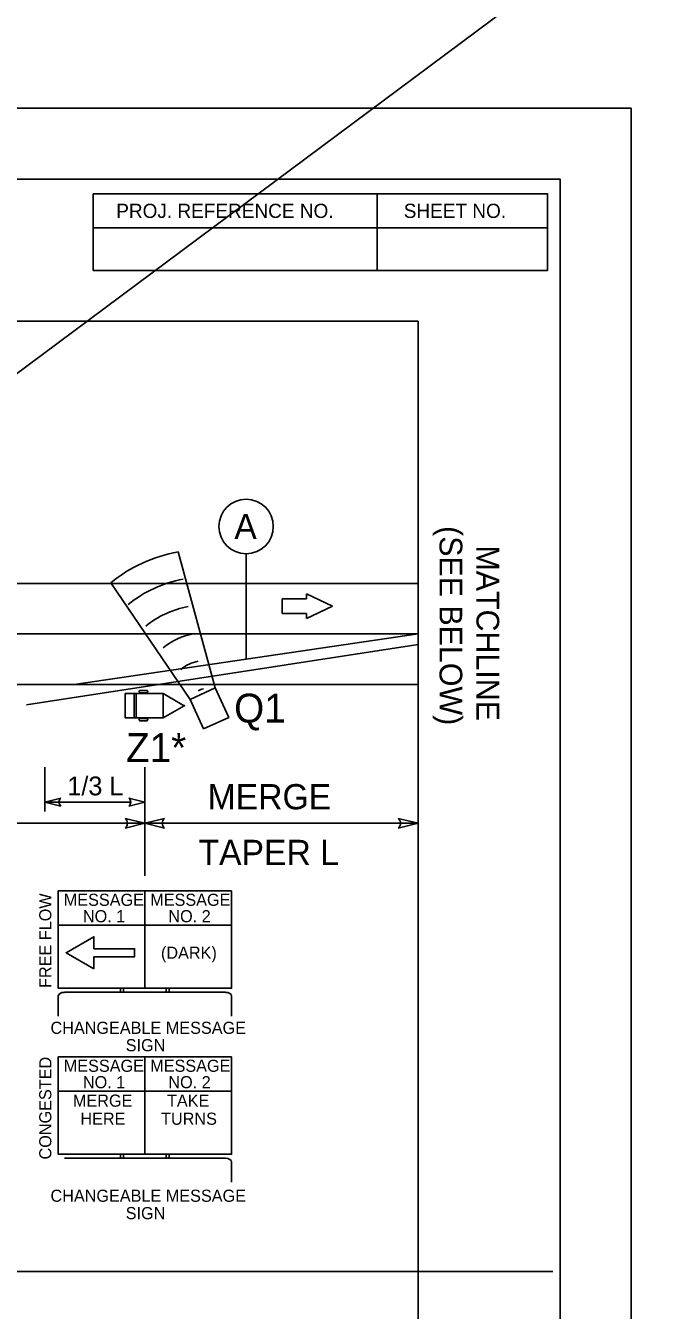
# Model space of a CAD drawing. Extents: x 1379436 to 1387057, y 792703 to 795604.
# Drawn here: x 1382289 to 1382626, y 794247 to 794926 of the extents above; entities that cross this region are included whole.
import ezdxf

# ---------------------------------------------------------------- set-up
doc = ezdxf.new("R2010")
doc.units = 0
for name, color, linetype in [('Black Area Fill Shapes', 7, 'Continuous'), ('Default', 7, 'Continuous'), ('DEV BORDER CELL', 7, 'Continuous'), ('DEV CMS PLAN VIEW CELL', 7, 'Continuous'), ('DEV CMS TEXT CELL', 7, 'Continuous'), ('DEV DIRECTION OF TRAFFIC FLOW ARROW CELL', 7, 'Continuous'), ('DEV LINE TERMINATOR TYPE 3 CELL', 7, 'Continuous'), ('Drum Linestyle', 7, 'Continuous'), ('Gray Area Fill Shapes', 7, 'Continuous'), ('Prop Mkg Skp Wht', 7, 'Continuous'), ('Prop Mkg Solid White Lane Line', 7, 'Continuous'), ('Prop Mkg Solid Yellow Edge Line', 7, 'Continuous'), ('Scratch_Level_0', 7, 'Continuous'), ('Sheet Plot Border Outside CELL', 7, 'Continuous'), ('Text', 7, 'Continuous')]:
    doc.layers.add(name, color=color, linetype=linetype)

msp = doc.modelspace()

# ---------------------------------------------------------------- linework, layer by layer
at = {"layer": 'Black Area Fill Shapes'}
msp.add_lwpolyline([(1382382.51, 794554.35), (1382375.35, 794569.89), (1382388.66, 794576.02), (1382395.82, 794560.48)], close=True, dxfattribs=at)
at = {"layer": 'Default'}
for p, q in [((1379547.85, 792703.35), (1383441.11, 795604.31)), ((1382495.75, 794522.98), (1382495.75, 794686.06)), ((1382404.97, 794591.19), (1382404.97, 794646.92)), ((1382298.74, 794534.09), (1382298.74, 794510.68)), ((1382351.53, 794534.09), (1382351.53, 794476.77)), ((1382495.75, 794534.09), (1382495.75, 794476.77)), ((1382298.74, 794515.71), (1382344.07, 794515.71)), ((1380845.89, 794504.52), (1382495.75, 794504.52)), ((1380316.98, 794267.83), (1382566.98, 794267.84))]:
    msp.add_line(p, q, dxfattribs=at)
msp.add_circle((1382404.97, 794661.28), 14.37, dxfattribs=at)
at = {"layer": 'DEV BORDER CELL'}
msp.add_line((1382474.23, 794819), (1382564.22, 794819), dxfattribs=at)
for points in [[(1382570.75, 794844.71), (1380320.75, 794844.71), (1380320.75, 793269.71), (1382570.75, 793269.71)], [(1382324.22, 794837), (1382474.23, 794837), (1382474.23, 794819), (1382324.22, 794819)], [(1382474.23, 794819), (1382564.22, 794819), (1382564.22, 794837), (1382474.23, 794837)], [(1382474.23, 794819), (1382324.22, 794819), (1382324.22, 794796.5), (1382474.23, 794796.5)], [(1382474.23, 794819), (1382564.22, 794819), (1382564.22, 794796.5), (1382474.23, 794796.5)]]:
    msp.add_lwpolyline(points, close=True, dxfattribs=at)
at = {"layer": 'DEV CMS PLAN VIEW CELL'}
for p, q in [((1382341.11, 794573.06), (1382341.11, 794560.14)), ((1382341.11, 794573.05), (1382361.1, 794573.05)), ((1382341.11, 794560.13), (1382341.11, 794573.05)), ((1382345.78, 794560.13), (1382345.78, 794573.05)), ((1382346.85, 794560.13), (1382346.85, 794573.05)), ((1382348.66, 794574.69), (1382352.79, 794574.69)), ((1382348.66, 794573.46), (1382352.79, 794573.46)), ((1382361.1, 794560.14), (1382361.1, 794573.05)), ((1382361.1, 794573.05), (1382372.29, 794566.6)), ((1382361.1, 794560.14), (1382372.29, 794566.6)), ((1382341.11, 794560.14), (1382361.1, 794560.14)), ((1382348.66, 794559.88), (1382352.79, 794559.88)), ((1382348.66, 794558.7), (1382352.79, 794558.7))]:
    msp.add_line(p, q, dxfattribs=at)
msp.add_circle((1382372.4, 794566.58), 0.114, dxfattribs=at)
for centre, start, end in [((1382349.41, 794574.05), 142.08835, 217.91165), ((1382352.03, 794574.05), 322.08835, 37.91165), ((1382349.41, 794559.29), 142.08835, 217.91165), ((1382352.03, 794559.29), 322.08835, 37.91165)]:
    msp.add_arc(centre, 0.954, start, end, dxfattribs=at)
at = {"layer": 'DEV CMS TEXT CELL'}
for p, q in [((1382305.77, 794468.84), (1382397.29, 794468.84)), ((1382305.77, 794417.37), (1382305.77, 794468.84)), ((1382351.53, 794417.37), (1382351.53, 794468.84)), ((1382351.53, 794417.37), (1382351.53, 794468.84)), ((1382397.29, 794417.37), (1382397.29, 794468.84)), ((1382305.77, 794450.73), (1382351.53, 794450.73)), ((1382397.29, 794450.73), (1382351.53, 794450.73)), ((1382397.29, 794417.37), (1382305.77, 794417.37)), ((1382308.98, 794415.24), (1382394.07, 794415.24)), ((1382338.67, 794417.37), (1382338.67, 794415.24)), ((1382340.25, 794417.37), (1382340.25, 794415.24)), ((1382362.82, 794417.37), (1382362.82, 794415.24)), ((1382364.4, 794417.37), (1382364.4, 794415.24)), ((1382305.77, 794413.24), (1382305.77, 794402.62)), ((1382397.31, 794413.25), (1382397.31, 794402.63)), ((1382305.77, 794381.18), (1382397.29, 794381.18)), ((1382305.77, 794329.7), (1382305.77, 794381.18)), ((1382351.53, 794329.7), (1382351.53, 794381.18)), ((1382351.53, 794329.7), (1382351.53, 794381.18)), ((1382397.29, 794329.7), (1382397.29, 794381.18)), ((1382305.77, 794363.07), (1382351.53, 794363.07)), ((1382397.29, 794363.07), (1382351.53, 794363.07)), ((1382397.29, 794329.7), (1382305.77, 794329.7)), ((1382308.98, 794327.57), (1382394.07, 794327.57)), ((1382338.67, 794329.7), (1382338.67, 794327.57)), ((1382340.25, 794329.7), (1382340.25, 794327.57)), ((1382362.82, 794329.7), (1382362.82, 794327.57)), ((1382364.4, 794329.7), (1382364.4, 794327.57)), ((1382397.31, 794325.59), (1382397.31, 794314.97))]:
    msp.add_line(p, q, dxfattribs=at)
msp.add_lwpolyline([(1382324.6, 794427.67), (1382309.91, 794436.15), (1382324.6, 794444.63), (1382324.6, 794438.28), (1382346.1, 794438.28), (1382346.1, 794434.02), (1382324.6, 794434.02)], close=True, dxfattribs=at)
for centre, major_axis, start_param, end_param in [((1382309, 794413.25), (-3.24, 0), 4.712389, 6.283185), ((1382394.07, 794413.25), (3.24, 0), 0, 1.570796), ((1382394.07, 794325.59), (3.24, 0), 0, 1.570796)]:
    msp.add_ellipse(centre, major_axis=major_axis, ratio=0.606795, start_param=start_param, end_param=end_param, dxfattribs=at)
at = {"layer": 'DEV DIRECTION OF TRAFFIC FLOW ARROW CELL'}
for p, q in [((1382450.55, 794619.24), (1382436.8, 794625.73)), ((1382436.8, 794625.73), (1382436.8, 794623.1)), ((1382424.02, 794623.11), (1382424.01, 794615.4)), ((1382436.8, 794623.1), (1382424.02, 794623.11)), ((1382436.79, 794612.77), (1382450.55, 794619.24)), ((1382424.01, 794615.4), (1382436.79, 794615.39)), ((1382436.79, 794615.39), (1382436.79, 794612.77))]:
    msp.add_line(p, q, dxfattribs=at)
at = {"layer": 'DEV LINE TERMINATOR TYPE 3 CELL'}
for points in [[(1382307.16, 794513.6), (1382298.74, 794515.71), (1382307.16, 794517.81)], [(1382307.16, 794513.6), (1382298.74, 794515.71), (1382307.16, 794517.81)], [(1382343.11, 794513.6), (1382351.53, 794515.71), (1382343.11, 794517.81)], [(1382343.11, 794513.6), (1382351.53, 794515.71), (1382343.11, 794517.81)], [(1382341.14, 794501.92), (1382351.53, 794504.52), (1382341.14, 794507.12)], [(1382341.14, 794501.92), (1382351.53, 794504.52), (1382341.14, 794507.12)], [(1382361.93, 794501.92), (1382351.53, 794504.52), (1382361.93, 794507.12)], [(1382361.93, 794501.92), (1382351.53, 794504.52), (1382361.93, 794507.12)], [(1382485.36, 794501.92), (1382495.75, 794504.52), (1382485.36, 794507.12)], [(1382485.36, 794501.92), (1382495.75, 794504.52), (1382485.36, 794507.12)]]:
    msp.add_lwpolyline(points, dxfattribs=at)
for centre, radius, start, end in [((1382309.01, 794515.71), 2.8, 131.32643, 228.67356), ((1382309.01, 794515.71), 2.8, 131.32643, 228.67356), ((1382341.26, 794515.71), 2.8, 311.32644, 48.67357), ((1382341.26, 794515.71), 2.8, 311.32644, 48.67357), ((1382338.85, 794504.52), 3.46, 311.32644, 48.67357), ((1382338.85, 794504.52), 3.46, 311.32644, 48.67357), ((1382364.21, 794504.52), 3.46, 131.32643, 228.67356), ((1382364.21, 794504.52), 3.46, 131.32643, 228.67356), ((1382483.07, 794504.52), 3.46, 311.32644, 48.67357), ((1382483.07, 794504.52), 3.46, 311.32644, 48.67357)]:
    msp.add_arc(centre, radius, start, end, dxfattribs=at)
at = {"layer": 'Drum Linestyle'}
msp.add_line((1382495.75, 794599.03), (1382289.02, 794567.01), dxfattribs=at)
at = {"layer": 'Gray Area Fill Shapes'}
for points in [[(1382351.53, 794450.73), (1382305.77, 794450.73), (1382305.77, 794417.37), (1382351.53, 794417.37)], [(1382351.53, 794450.73), (1382397.29, 794450.73), (1382397.29, 794417.37), (1382351.53, 794417.37)], [(1382351.53, 794363.07), (1382305.77, 794363.07), (1382305.77, 794329.7), (1382351.53, 794329.7)], [(1382351.53, 794363.07), (1382397.29, 794363.07), (1382397.29, 794329.7), (1382351.53, 794329.7)]]:
    msp.add_lwpolyline(points, close=True, dxfattribs=at)
at = {"layer": 'Prop Mkg Skp Wht'}
msp.add_line((1381406.39, 794604.5), (1382495.75, 794604.51), dxfattribs=at)
at = {"layer": 'Prop Mkg Solid White Lane Line'}
for p, q in [((1382495.75, 794604.51), (1382314.19, 794577.88)), ((1381406.39, 794577.88), (1382495.75, 794577.88))]:
    msp.add_line(p, q, dxfattribs=at)
at = {"layer": 'Prop Mkg Solid Yellow Edge Line'}
msp.add_line((1381406.39, 794631.12), (1382495.75, 794631.12), dxfattribs=at)
at = {"layer": 'Scratch_Level_0'}
msp.add_lwpolyline([(1382495.75, 794769.71), (1380395.75, 794769.71), (1380395.75, 793344.71), (1381714.03, 793344.71), (1381714.03, 793522.11), (1382495.75, 793522.11)], close=True, dxfattribs=at)
at = {"layer": 'Sheet Plot Border Outside CELL'}
msp.add_lwpolyline([(1380076.25, 793232.21), (1382608.25, 793232.21), (1382608.25, 794882.21), (1380076.25, 794882.21)], close=True, dxfattribs=at)
at = {"layer": 'Text'}
for p, q in [((1382388.66, 794576.02), (1382369.02, 794647.92)), ((1382375.35, 794569.89), (1382333.45, 794631.53))]:
    msp.add_line(p, q, dxfattribs=at)
for radius in [79.44, 64.74, 50.04, 35.34, 20.63, 5.93]:
    msp.add_arc((1382383.46, 794569.79), radius, 100.47314, 129.0092, dxfattribs=at)

# ---------------------------------------------------------------- texts
at = {"layer": 'Default'}
for s, p in [('(SEE BELOW)', (1382507.12, 794661.51)), ('MATCHLINE', (1382526.62, 794651.28))]:
    msp.add_text(s, height=12, rotation=270, dxfattribs=at).set_placement(p)
at = {"layer": 'DEV BORDER CELL'}
for s, height, p in [('PROJ. REFERENCE NO.', 7.4988, (1382336.39, 794824.25)), ('SHEET NO.', 7.499, (1382488.22, 794824.25))]:
    msp.add_text(s, height=height, rotation=0.00056, dxfattribs=at).set_placement(p)
at = {"layer": 'DEV CMS TEXT CELL'}
for s, rotation, p in [('FREE FLOW', 90, (1382302.12, 794417.55)), ('MESSAGE', 360, (1382354.33, 794460.92)), ('NO. 2', 360, (1382363.91, 794452.25)), ('CONGESTED', 90, (1382302.12, 794326.94)), ('MESSAGE', 360, (1382354.33, 794373.25)), ('NO. 2', 360, (1382363.91, 794364.58))]:
    msp.add_text(s, height=6.403, rotation=rotation, dxfattribs=at).set_placement(p)
for s, height, p in [('MESSAGE', 6.403, (1382308.67, 794460.92)), ('NO. 1', 6.403, (1382318.78, 794452.25)), ('(DARK)', 6.403, (1382360.01, 794432.95)), ('CHANGEABLE MESSAGE', 6.4025, (1382301.66, 794393.3)), ('SIGN', 6.403, (1382341.39, 794384.11)), ('MESSAGE', 6.403, (1382308.67, 794373.25)), ('NO. 1', 6.403, (1382318.78, 794364.58)), ('MERGE', 6.403, (1382313.51, 794354.82)), ('TAKE', 6.403, (1382363.18, 794354.82)), ('HERE', 6.403, (1382317.46, 794345.28)), ('TURNS', 6.403, (1382360.07, 794345.28)), ('CHANGEABLE MESSAGE', 6.4025, (1382301.66, 794304.6)), ('SIGN', 6.403, (1382341.39, 794295.41))]:
    msp.add_text(s, height=height, dxfattribs=at).set_placement(p)
at = {"layer": 'Text'}
for s, height, p in [('A', 13.31, (1382398.75, 794654.63)), ('Q1', 15.29, (1382398.63, 794557.7)), ('Z1*', 15.29, (1382341.53, 794536.84)), ('1/3 L', 9.942, (1382310.59, 794519.28)), ('MERGE ', 13.31, (1382384.64, 794511.9)), ('TAPER L', 13.31, (1382379.82, 794482.48))]:
    msp.add_text(s, height=height, dxfattribs=at).set_placement(p)

doc.saveas('drawing.dxf')
